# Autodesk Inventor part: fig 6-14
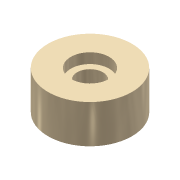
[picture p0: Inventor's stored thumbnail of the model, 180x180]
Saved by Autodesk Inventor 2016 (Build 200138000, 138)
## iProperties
Shininess: 65.0
Angle Display Precision: 2
Document Length Units: 11269
Document Angle Units: 11279
Document Time Units: 11290
Document Mass Units: 11283
Document Length Units Precision: 3
Document Angle Units Precision: 2
Created: 2001-11
Part Number: fig 6-14
Document SubType Name: Modeling
Designer: Renu Muthoo
Density: 1 g/cm^3
Material: Generic
Appearance: Metal-Titanium (Polished)
Density: 0.0
Volumn: 0.0
Area: 0.0
PropertySet Name: Model Information
Control State: 0
Master: False
Checked Out: False
Author: Renu Muthoo
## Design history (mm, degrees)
sketch "Sketch1"
  geometry: C1 r 16.401 at (0, 0)
  constraints: 1 centre point
extrude "Extrusion1" new body sketch "Sketch1" distance "d0" = 15; taper "d1" = 0 deg
hole "Hole3" diameter "d18" = 10.106; stored, may be unused: countersink angle "d22" = 90 deg, drill point angle "d24" = 118 deg; dims "d16" = 10, "d17" = 10, "d19" = 6, "d20" = 15, "d21" = 4, "d23" = 10
body "Solid1"
